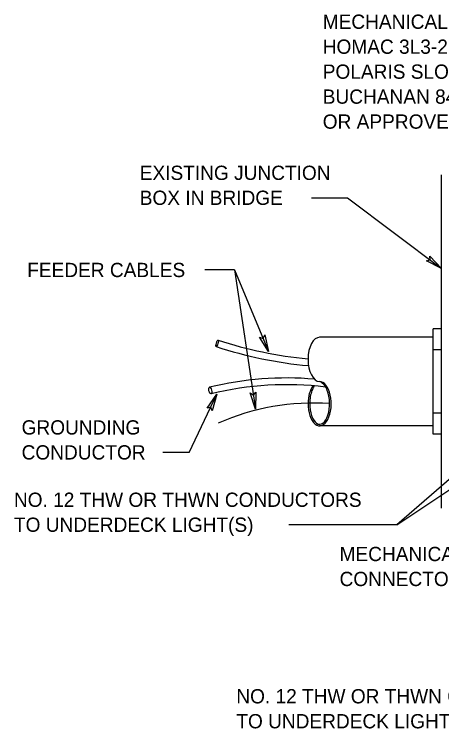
# Model space of a CAD drawing. Extents: x 99981 to 128681, y 99783 to 102182.
# Drawn here: x 126329 to 126689, y 100532 to 101136 of the extents above; entities that cross this region are included whole.
import ezdxf

# ---------------------------------------------------------------- set-up
doc = ezdxf.new("R2010")
doc.units = 0
doc.layers.add('Level 1', color=7, linetype='Continuous')

msp = doc.modelspace()

# ---------------------------------------------------------------- linework, layer by layer
at = {"layer": 'Level 1'}
for p, q in [((126688.51, 100721.17), (126688.51, 101001.42)), ((126579.16, 100982.17), (126609.32, 100982.17)), ((126609.32, 100982.17), (126688.51, 100922.71)), ((126514.41, 100921.46), (126489.44, 100921.46)), ((126514.41, 100921.46), (126542.87, 100852.94)), ((126514.41, 100921.46), (126532.03, 100804.43)), ((126681.41, 100783.25), (126681.41, 100871.94)), ((126688.51, 100871.94), (126681.41, 100871.94)), ((126681.41, 100864.85), (126585.9, 100864.85)), ((126688.51, 100854.2), (126681.41, 100854.2)), ((126476.06, 100768.04), (126499.48, 100816.86)), ((126771.12, 100811.34), (126650.92, 100707.2)), ((126688.51, 100800.99), (126681.41, 100800.99)), ((126681.41, 100790.35), (126585.9, 100790.35)), ((126650.92, 100707.2), (126773.02, 100788.5)), ((126688.51, 100783.25), (126681.41, 100783.25)), ((126476.06, 100768.04), (126454.08, 100768.04)), ((126650.92, 100707.2), (126560.05, 100707.2))]:
    msp.add_line(p, q, dxfattribs=at)
for points in [[(126678.67, 100933.1), (126688.51, 100922.71), (126675.79, 100929.27), (126679, 100929.85)], [(126539.67, 100866.88), (126542.87, 100852.94), (126535.25, 100865.05), (126538.31, 100863.92)], [(126491.22, 100805.18), (126499.48, 100816.86), (126495.54, 100803.11), (126494.33, 100806.14)], [(126532.3, 100818.73), (126532.03, 100804.43), (126527.56, 100818.01), (126530.26, 100816.18)]]:
    msp.add_lwpolyline(points, close=True, dxfattribs=at)
for centre, radius, start, end in [((126608.53, 101192), 346.8, 251.86185, 264.64343), ((126608.53, 101192), 352.48, 251.86185, 264.79334), ((126558.07, 100556.87), 273.75, 85.06497, 103.70196), ((126581.31, 100817.16), 11.4, 14.95568, 66.23797), ((126558.07, 100556.87), 268.07, 82.99334, 103.70196), ((126590.63, 100817.02), 11.58, 143.73549, 164.97996), ((126580.41, 100613.91), 195.63, 85.91545, 114.08578)]:
    msp.add_arc(centre, radius, start, end, dxfattribs=at)
for centre, major_axis, ratio, start_param, end_param in [((126585.91, 100846.26), (0, 18.62), 0.524286, 6.280756, 9.416123), ((126585.91, 100808.97), (0, 18.62), 0.524286, 1.545371, 6.30551), ((126585.91, 100808.97), (0, 18.62), 0.524286, 0.637695, 1.553344), ((126585.91, 100808.97), (0, 17.26), 0.486783, 1.540782, 5.413234), ((126585.91, 100808.97), (0, 17.26), 0.486783, 0.876011, 1.540782)]:
    msp.add_ellipse(centre, major_axis=major_axis, ratio=ratio, start_param=start_param, end_param=end_param, dxfattribs=at)
for centre, major_axis, ratio in [((126499.68, 100859.73), (0.88, 2.7), 0.240996), ((126493.9, 100820.07), (-0.67, 2.76), 0.405047)]:
    msp.add_ellipse(centre, major_axis=major_axis, ratio=ratio, dxfattribs=at)

# ---------------------------------------------------------------- texts
for s, p in [('MECHANICAL CABLE CONNECTOR', (126588.5, 101124.26)), ('HOMAC 3L3-2K', (126588.5, 101103.26)), ('POLARIS SLOWB2/0-21P', (126588.5, 101082.26)), ('BUCHANAN 84S-ADB1', (126588.5, 101061.26)), ('OR APPROVED EQUAL ', (126588.5, 101040.26)), ('EXISTING JUNCTION ', (126434.59, 100997.17)), ('BOX IN BRIDGE ', (126434.59, 100976.17)), ('FEEDER CABLES ', (126339.94, 100915.46)), ('GROUNDING ', (126335.22, 100783.04)), ('CONDUCTOR ', (126335.22, 100762.04)), ('NO. 12 THW OR THWN CONDUCTORS', (126328.78, 100722.2)), ('TO UNDERDECK LIGHT(S) ', (126328.78, 100701.2)), ('MECHANICAL GROUNDING', (126602.65, 100676.58)), ('CONNECTOR ', (126602.65, 100655.58)), ('NO. 12 THW OR THWN CONDUCTORS', (126515.82, 100556.93)), ('TO UNDERDECK LIGHT(S) ', (126515.82, 100535.93))]:
    msp.add_text(s, height=12, dxfattribs=at).set_placement(p)

doc.saveas('drawing.dxf')
